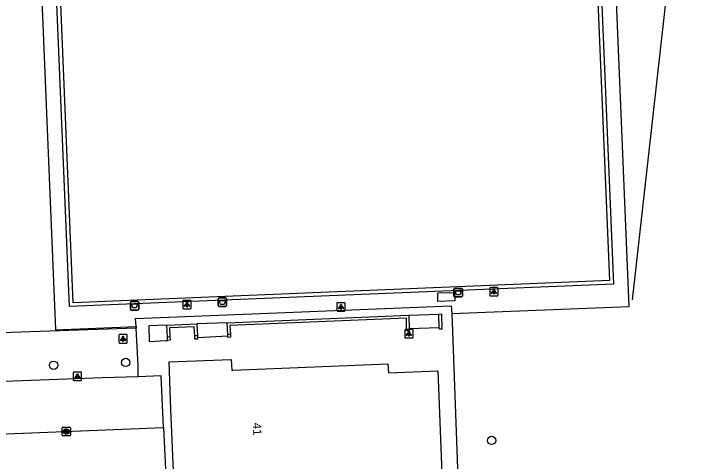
# Model space of a CAD drawing. Extents: x 162515 to 163909, y 388494 to 389773.
# Drawn here: x 162602.9 to 162685.2, y 388732.4 to 388785.1 of the extents above; entities that cross this region are included whole.
import ezdxf

# ---------------------------------------------------------------- set-up
doc = ezdxf.new("R2010")
doc.units = 0
for name, color, linetype in [('IMGEO_Afvalbak', 7, 'Continuous'), ('IMGEO_Boom', 7, 'Continuous'), ('IMGEO_Groenvoorziening', 7, 'Continuous'), ('IMGEO_Hek', 7, 'Continuous'), ('IMGEO_Kolk', 7, 'Continuous'), ('IMGEO_Lichtpunt', 7, 'Continuous'), ('IMGEO_Muur', 7, 'Continuous'), ('IMGEO_Pand', 7, 'Continuous'), ('IMGEO_Pand_nummerreeks', 7, 'Continuous'), ('IMGEO_Parkeervlak_open', 7, 'Continuous'), ('IMGEO_Voetpad_open', 7, 'Continuous')]:
    doc.layers.add(name, color=color, linetype=linetype)

msp = doc.modelspace()

# ---------------------------------------------------------------- linework, layer by layer
at = {"layer": 'IMGEO_Afvalbak'}
for p, q in [((162654.687, 388751.859), (162654.687, 388752.659)), ((162654.687, 388752.659), (162654.687, 388751.859)), ((162654.787, 388752.759), (162655.577, 388752.759)), ((162655.577, 388752.759), (162654.787, 388752.759)), ((162655.677, 388752.659), (162655.677, 388751.859)), ((162655.677, 388751.859), (162655.677, 388752.659)), ((162626.921, 388750.737), (162626.921, 388751.537)), ((162626.921, 388751.537), (162626.921, 388750.737)), ((162627.021, 388751.637), (162627.811, 388751.637)), ((162627.811, 388751.637), (162627.021, 388751.637)), ((162627.911, 388751.537), (162627.911, 388750.737)), ((162627.911, 388750.737), (162627.911, 388751.537)), ((162655.577, 388751.759), (162654.787, 388751.759)), ((162654.787, 388751.759), (162655.577, 388751.759)), ((162616.578, 388750.314), (162616.578, 388751.114)), ((162616.578, 388751.114), (162616.578, 388750.314)), ((162616.678, 388751.214), (162617.468, 388751.214)), ((162617.468, 388751.214), (162616.678, 388751.214)), ((162617.568, 388751.114), (162617.568, 388750.314)), ((162617.568, 388750.314), (162617.568, 388751.114)), ((162617.468, 388750.214), (162616.678, 388750.214)), ((162616.678, 388750.214), (162617.468, 388750.214)), ((162627.811, 388750.637), (162627.021, 388750.637)), ((162627.021, 388750.637), (162627.811, 388750.637))]:
    msp.add_line(p, q, dxfattribs=at)
for points in [[(162654.83, 388752.473), (162655.534, 388752.473), (162655.385, 388752.003), (162654.979, 388752.003), (162654.83, 388752.473)], [(162616.721, 388750.928), (162617.425, 388750.928), (162617.276, 388750.458), (162616.87, 388750.458), (162616.721, 388750.928)], [(162627.064, 388751.351), (162627.768, 388751.351), (162627.619, 388750.881), (162627.213, 388750.881), (162627.064, 388751.351)]]:
    msp.add_lwpolyline(points, dxfattribs=at)
for centre, start, end in [((162654.787, 388752.659), 90, 180), ((162654.787, 388752.659), 90, 180), ((162655.577, 388752.659), 0, 90), ((162655.577, 388752.659), 360, 90), ((162627.021, 388751.537), 90, 180), ((162627.021, 388751.537), 90, 180), ((162627.811, 388751.537), 0, 90), ((162627.811, 388751.537), 360, 90), ((162654.787, 388751.859), 180, 270), ((162654.787, 388751.859), 180, 270), ((162655.577, 388751.859), 270, 0), ((162655.577, 388751.859), 270, 0), ((162616.678, 388751.114), 90, 180), ((162616.678, 388751.114), 90, 180), ((162617.468, 388751.114), 0, 90), ((162617.468, 388751.114), 360, 90), ((162627.021, 388750.737), 180, 270), ((162627.021, 388750.737), 180, 270), ((162627.811, 388750.737), 270, 0), ((162627.811, 388750.737), 270, 0), ((162616.678, 388750.314), 180, 270), ((162616.678, 388750.314), 180, 270), ((162617.468, 388750.314), 270, 0), ((162617.468, 388750.314), 270, 0)]:
    msp.add_arc(centre, 0.1, start, end, dxfattribs=at)
at = {"layer": 'IMGEO_Boom'}
for centre in [(162607.538, 388743.725), (162616.024, 388744.043), (162659.135, 388734.868)]:
    msp.add_circle(centre, 0.489, dxfattribs=at)
at = {"layer": 'IMGEO_Groenvoorziening'}
msp.add_lwpolyline([(162617.26, 388748.066), (162576.503, 388746.666), (162571.458, 388901.227), (162571.544, 388901.823), (162571.936, 388902.521), (162572.399, 388902.907), (162573.157, 388903.164)], dxfattribs=at)
at = {"layer": 'IMGEO_Hek'}
for points in [[(162675.706, 388751.411), (162685.197, 388836.109)], [(162609.41, 388750.613), (162606.241, 388826.64), (162670.312, 388829.303), (162673.469, 388753.257), (162609.41, 388750.613)]]:
    msp.add_lwpolyline(points, dxfattribs=at)
at = {"layer": 'IMGEO_Kolk'}
for p, q in [((162608.536, 388735.485), (162608.536, 388736.337)), ((162608.611, 388736.411), (162609.463, 388736.411)), ((162609.024, 388736.191), (162609.049, 388736.191)), ((162609.537, 388736.337), (162609.537, 388735.485)), ((162609.463, 388735.411), (162608.611, 388735.411)), ((162609.047, 388735.631), (162609.022, 388735.631))]:
    msp.add_line(p, q, dxfattribs=at)
for points in [[(162608.536, 388735.485), (162608.536, 388736.337)], [(162608.611, 388736.411), (162609.463, 388736.411)], [(162608.857, 388736.111), (162608.98, 388736.111), (162608.98, 388735.96), (162609.11, 388736.111), (162609.274, 388736.111), (162609.128, 388735.96), (162609.281, 388735.711), (162609.129, 388735.711), (162609.044, 388735.875), (162608.98, 388735.808), (162608.98, 388735.711), (162608.857, 388735.711), (162608.857, 388736.111)], [(162609.537, 388736.337), (162609.537, 388735.485)], [(162609.463, 388735.411), (162608.611, 388735.411)]]:
    msp.add_lwpolyline(points, dxfattribs=at)
for centre, start, end in [((162608.613, 388736.335), 91.55205, 178.44795), ((162608.613, 388736.335), 91.55205, 178.44795), ((162609.461, 388736.335), 1.55205, 88.44795), ((162609.461, 388736.335), 1.55205, 88.44795), ((162608.613, 388735.487), 181.55205, 268.44795), ((162608.613, 388735.487), 181.55205, 268.44795), ((162609.461, 388735.487), 271.55205, 358.44795), ((162609.461, 388735.487), 271.55205, 358.44795)]:
    msp.add_arc(centre, 0.0765, start, end, dxfattribs=at)
for centre, major_axis, ratio, start_param, end_param in [((162609.023, 388735.911), (-0.387, 0.002), 0.722429, 4.712389, 7.853982), ((162609.048, 388735.911), (-0.39, 0.002), 0.717154, 1.570796, 4.712389)]:
    msp.add_ellipse(centre, major_axis=major_axis, ratio=ratio, start_param=start_param, end_param=end_param, dxfattribs=at)
at = {"layer": 'IMGEO_Lichtpunt'}
for p, q in [((162658.895, 388752.772), (162658.895, 388751.965)), ((162658.895, 388752.772), (162658.895, 388751.965)), ((162659.797, 388752.867), (162658.989, 388752.867)), ((162659.797, 388752.867), (162658.989, 388752.867)), ((162659.891, 388751.965), (162659.891, 388752.772)), ((162659.891, 388751.965), (162659.891, 388752.772)), ((162658.989, 388751.871), (162659.797, 388751.871)), ((162658.989, 388751.871), (162659.797, 388751.871)), ((162622.749, 388751.259), (162622.749, 388750.452)), ((162622.749, 388751.259), (162622.749, 388750.452)), ((162623.651, 388751.354), (162622.843, 388751.354)), ((162623.651, 388751.354), (162622.843, 388751.354)), ((162623.745, 388750.452), (162623.745, 388751.259)), ((162623.745, 388750.452), (162623.745, 388751.259)), ((162640.887, 388750.979), (162640.887, 388750.172)), ((162640.887, 388750.979), (162640.887, 388750.172)), ((162641.789, 388751.074), (162640.981, 388751.074)), ((162641.789, 388751.074), (162640.981, 388751.074)), ((162641.883, 388750.172), (162641.883, 388750.979)), ((162641.883, 388750.172), (162641.883, 388750.979)), ((162622.843, 388750.358), (162623.651, 388750.358)), ((162622.843, 388750.358), (162623.651, 388750.358)), ((162640.981, 388750.078), (162641.789, 388750.078)), ((162640.981, 388750.078), (162641.789, 388750.078)), ((162648.885, 388747.827), (162648.885, 388747.02)), ((162648.885, 388747.827), (162648.885, 388747.02)), ((162649.787, 388747.922), (162648.979, 388747.922)), ((162649.787, 388747.922), (162648.979, 388747.922)), ((162649.881, 388747.02), (162649.881, 388747.827)), ((162649.881, 388747.02), (162649.881, 388747.827)), ((162615.221, 388747.227), (162615.221, 388746.42)), ((162615.221, 388747.227), (162615.221, 388746.42)), ((162616.123, 388747.322), (162615.315, 388747.322)), ((162616.123, 388747.322), (162615.315, 388747.322)), ((162616.217, 388746.42), (162616.217, 388747.227)), ((162616.217, 388746.42), (162616.217, 388747.227)), ((162648.979, 388746.926), (162649.787, 388746.926)), ((162648.979, 388746.926), (162649.787, 388746.926)), ((162615.315, 388746.326), (162616.123, 388746.326)), ((162615.315, 388746.326), (162616.123, 388746.326)), ((162609.847, 388742.818), (162609.847, 388742.011)), ((162609.847, 388742.818), (162609.847, 388742.011)), ((162610.749, 388742.913), (162609.941, 388742.913)), ((162610.749, 388742.913), (162609.941, 388742.913)), ((162610.843, 388742.011), (162610.843, 388742.818)), ((162610.843, 388742.011), (162610.843, 388742.818)), ((162609.941, 388741.917), (162610.749, 388741.917)), ((162609.941, 388741.917), (162610.749, 388741.917))]:
    msp.add_line(p, q, dxfattribs=at)
for points in [[(162659.269, 388752.436), (162659.308, 388752.408), (162659.12, 388752.146), (162659.082, 388752.173), (162659.269, 388752.436)], [(162659.371, 388752.388), (162659.418, 388752.388), (162659.418, 388752.066), (162659.371, 388752.066), (162659.371, 388752.388)], [(162659.481, 388752.408), (162659.519, 388752.435), (162659.706, 388752.173), (162659.667, 388752.145), (162659.481, 388752.408)], [(162623.123, 388750.923), (162623.162, 388750.895), (162622.974, 388750.633), (162622.936, 388750.66), (162623.123, 388750.923)], [(162623.225, 388750.875), (162623.272, 388750.875), (162623.272, 388750.553), (162623.225, 388750.553), (162623.225, 388750.875)], [(162623.335, 388750.895), (162623.373, 388750.922), (162623.56, 388750.66), (162623.521, 388750.632), (162623.335, 388750.895)], [(162641.261, 388750.643), (162641.3, 388750.615), (162641.112, 388750.353), (162641.074, 388750.38), (162641.261, 388750.643)], [(162641.363, 388750.595), (162641.41, 388750.595), (162641.41, 388750.273), (162641.363, 388750.273), (162641.363, 388750.595)], [(162641.473, 388750.615), (162641.511, 388750.642), (162641.698, 388750.38), (162641.659, 388750.352), (162641.473, 388750.615)], [(162649.259, 388747.491), (162649.298, 388747.463), (162649.11, 388747.201), (162649.072, 388747.228), (162649.259, 388747.491)], [(162649.361, 388747.443), (162649.408, 388747.443), (162649.408, 388747.121), (162649.361, 388747.121), (162649.361, 388747.443)], [(162649.471, 388747.463), (162649.509, 388747.49), (162649.696, 388747.228), (162649.657, 388747.2), (162649.471, 388747.463)], [(162615.595, 388746.891), (162615.634, 388746.863), (162615.446, 388746.601), (162615.408, 388746.628), (162615.595, 388746.891)], [(162615.697, 388746.843), (162615.744, 388746.843), (162615.744, 388746.521), (162615.697, 388746.521), (162615.697, 388746.843)], [(162615.807, 388746.863), (162615.845, 388746.89), (162616.032, 388746.628), (162615.993, 388746.6), (162615.807, 388746.863)], [(162610.221, 388742.482), (162610.26, 388742.454), (162610.072, 388742.192), (162610.034, 388742.219), (162610.221, 388742.482)], [(162610.433, 388742.454), (162610.471, 388742.481), (162610.658, 388742.219), (162610.619, 388742.191), (162610.433, 388742.454)], [(162610.323, 388742.434), (162610.37, 388742.434), (162610.37, 388742.112), (162610.323, 388742.112), (162610.323, 388742.434)]]:
    msp.add_lwpolyline(points, dxfattribs=at)
for centre in [(162659.394, 388752.57), (162623.248, 388751.057), (162641.386, 388750.777), (162649.384, 388747.625), (162615.72, 388747.025), (162610.346, 388742.616)]:
    msp.add_circle(centre, 0.0994, dxfattribs=at)
for centre, start, end in [((162658.989, 388752.772), 90, 180), ((162658.989, 388752.772), 90, 180), ((162659.797, 388752.772), 0, 90), ((162659.797, 388752.772), 0, 90), ((162658.989, 388751.965), 180, 270), ((162658.989, 388751.965), 180, 270), ((162659.797, 388751.965), 270, 0), ((162659.797, 388751.965), 270, 360), ((162622.843, 388751.259), 90, 180), ((162622.843, 388751.259), 90, 180), ((162623.651, 388751.259), 0, 90), ((162623.651, 388751.259), 0, 90), ((162640.981, 388750.979), 90, 180), ((162640.981, 388750.979), 90, 180), ((162641.789, 388750.979), 0, 90), ((162641.789, 388750.979), 0, 90), ((162622.843, 388750.452), 180, 270), ((162622.843, 388750.452), 180, 270), ((162623.651, 388750.452), 270, 0), ((162623.651, 388750.452), 270, 360), ((162640.981, 388750.172), 180, 270), ((162640.981, 388750.172), 180, 270), ((162641.789, 388750.172), 270, 0), ((162641.789, 388750.172), 270, 360), ((162648.979, 388747.827), 90, 180), ((162648.979, 388747.827), 90, 180), ((162649.787, 388747.827), 0, 90), ((162649.787, 388747.827), 0, 90), ((162615.315, 388747.227), 90, 180), ((162615.315, 388747.227), 90, 180), ((162616.123, 388747.227), 0, 90), ((162616.123, 388747.227), 0, 90), ((162648.979, 388747.02), 180, 270), ((162648.979, 388747.02), 180, 270), ((162649.787, 388747.02), 270, 0), ((162649.787, 388747.02), 270, 360), ((162615.315, 388746.42), 180, 270), ((162615.315, 388746.42), 180, 270), ((162616.123, 388746.42), 270, 0), ((162616.123, 388746.42), 270, 360), ((162609.941, 388742.818), 90, 180), ((162609.941, 388742.818), 90, 180), ((162610.749, 388742.818), 0, 90), ((162610.749, 388742.818), 0, 90), ((162609.941, 388742.011), 180, 270), ((162609.941, 388742.011), 180, 270), ((162610.749, 388742.011), 270, 0), ((162610.749, 388742.011), 270, 360)]:
    msp.add_arc(centre, 0.0946, start, end, dxfattribs=at)
at = {"layer": 'IMGEO_Muur'}
for points in [[(162627.983, 388748.718), (162649.367, 388749.594)], [(162649.426, 388747.995), (162649.426, 388747.821), (162649.118, 388747.809), (162649.087, 388749.273), (162628.314, 388748.41), (162628.363, 388747.337)], [(162649.367, 388749.594), (162649.426, 388747.995)], [(162652.907, 388749.742), (162653.22, 388749.749), (162653.28, 388747.977), (162652.97, 388747.971), (162652.962, 388748.137)], [(162652.962, 388748.137), (162652.907, 388749.742)], [(162620.882, 388748.425), (162624.398, 388748.578)], [(162620.943, 388747.032), (162620.882, 388748.425)], [(162624.157, 388747.164), (162624.103, 388748.256), (162621.2, 388748.128), (162621.245, 388747.044)], [(162624.398, 388748.578), (162624.469, 388747.177)], [(162628.054, 388747.324), (162627.983, 388748.718)], [(162621.245, 388747.044), (162620.943, 388747.032)], [(162620.961, 388746.631), (162620.943, 388747.032)], [(162621.245, 388747.044), (162621.262, 388746.652), (162620.961, 388746.631)], [(162624.469, 388747.177), (162624.157, 388747.164)], [(162624.479, 388746.986), (162624.478, 388746.794), (162624.177, 388746.773), (162624.157, 388747.164)], [(162624.469, 388747.177), (162624.479, 388746.986)], [(162628.363, 388747.337), (162628.054, 388747.324)], [(162628.062, 388747.168), (162628.054, 388747.324)], [(162628.363, 388747.337), (162628.379, 388747.004), (162628.07, 388746.98), (162628.062, 388747.168)]]:
    msp.add_lwpolyline(points, dxfattribs=at)
at = {"layer": 'IMGEO_Pand'}
msp.add_lwpolyline([(162653.435, 388726.995), (162643.707, 388726.604), (162643.587, 388729.613), (162621.796, 388728.603), (162621.353, 388738.494), (162621.162, 388744.102), (162628.439, 388744.399), (162628.518, 388743.131), (162628.632, 388743.136), (162646.92, 388743.867), (162646.964, 388742.816), (162652.778, 388743.049), (162653.435, 388726.995)], dxfattribs=at)
at = {"layer": 'IMGEO_Parkeervlak_open'}
for points in [[(162617.482, 388742.368), (162613.301, 388742.225), (162579.691, 388740.996)], [(162577.66, 388734.646), (162620.485, 388736.373)]]:
    msp.add_lwpolyline(points, dxfattribs=at)
at = {"layer": 'IMGEO_Voetpad_open'}
for points in [[(162672.12, 388827.526), (162671.968, 388831.096), (162604.429, 388828.316), (162607.763, 388747.898), (162617.249, 388748.279)], [(162673.469, 388753.257), (162609.41, 388750.613), (162606.241, 388826.64), (162670.312, 388829.303), (162673.469, 388753.257)], [(162609.844, 388751.074), (162606.728, 388826.192), (162669.864, 388828.794), (162672.989, 388753.682), (162609.844, 388751.074)], [(162654.434, 388749.809), (162675.321, 388750.649), (162672.289, 388823.443)], [(162654.77, 388752.288), (162654.8, 388751.292), (162652.802, 388751.232), (162652.772, 388752.228), (162654.77, 388752.288)], [(162617.249, 388748.279), (162617.198, 388749.222), (162654.349, 388750.726), (162654.434, 388749.809)], [(162649.367, 388749.594), (162652.907, 388749.742)], [(162654.434, 388749.809), (162654.518, 388747.72), (162655.329, 388725.102), (162655.344, 388724.714)], [(162617.249, 388748.279), (162617.26, 388748.066)], [(162620.882, 388748.425), (162618.744, 388748.339), (162618.81, 388746.513), (162620.768, 388746.621), (162620.961, 388746.631)], [(162627.983, 388748.718), (162624.398, 388748.578)], [(162617.482, 388742.368), (162617.493, 388743.727), (162617.26, 388748.066)], [(162652.962, 388748.137), (162649.426, 388747.995)], [(162624.479, 388746.986), (162628.062, 388747.168)], [(162620.485, 388736.373), (162620.203, 388742.474), (162617.482, 388742.368)], [(162620.485, 388736.373), (162620.774, 388730.652)]]:
    msp.add_lwpolyline(points, dxfattribs=at)

# ---------------------------------------------------------------- texts
at = {"layer": 'IMGEO_Pand_nummerreeks'}
msp.add_text('41', height=1, rotation=272.30253, dxfattribs=at).set_placement((162631.003, 388736.933))

doc.saveas('drawing.dxf')
